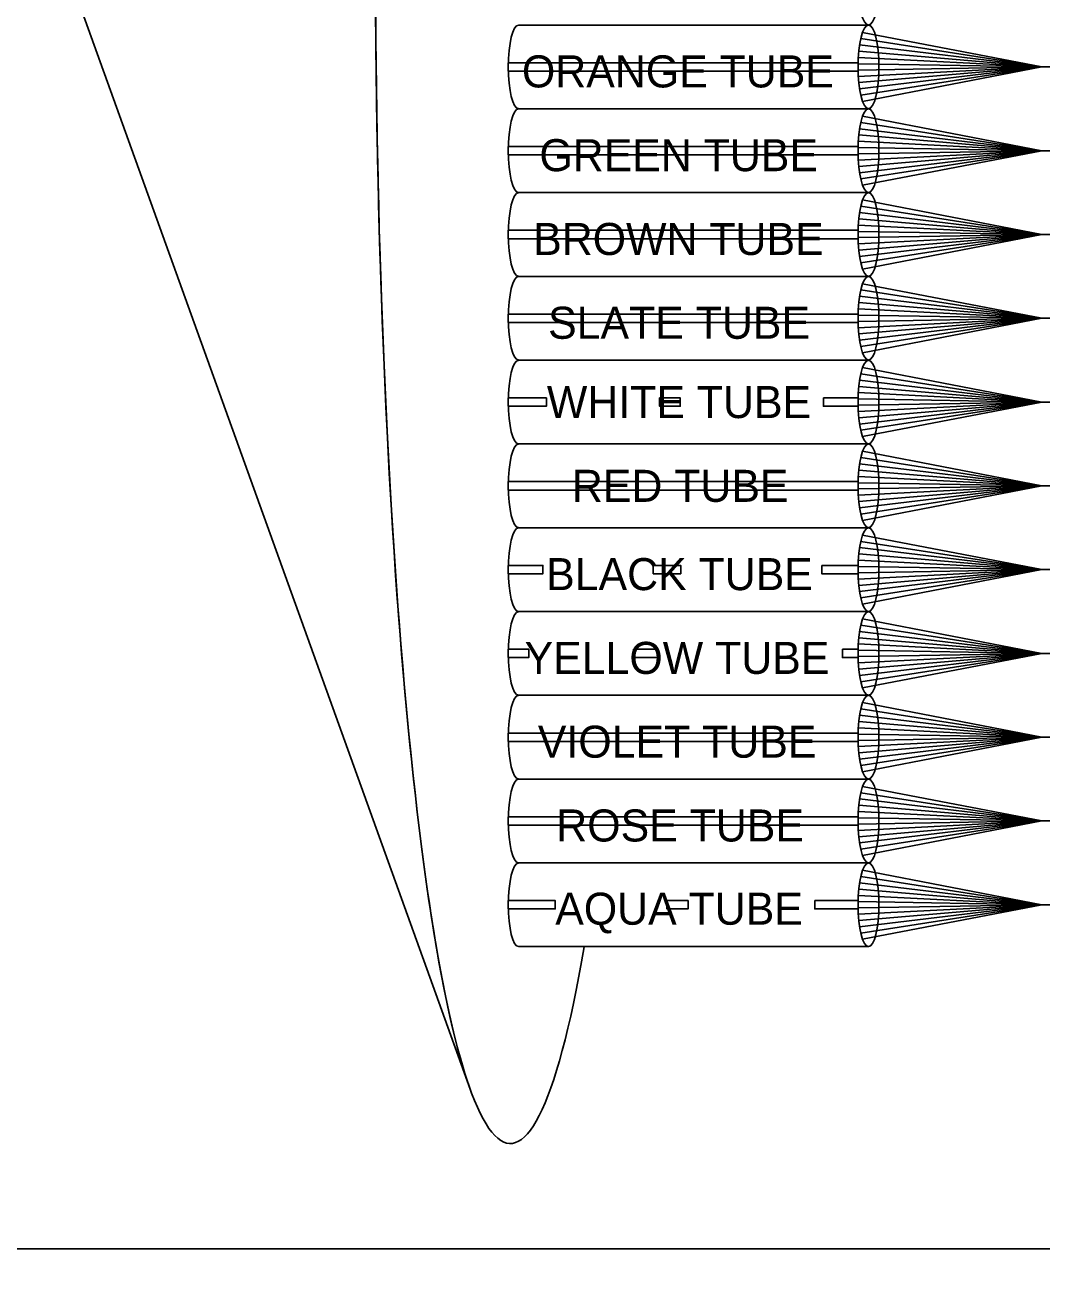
# Model space of a CAD drawing. Extents: x 1805893 to 1833564, y 708898 to 716199.
# Drawn here: x 1831609.4 to 1831682.2, y 715310.4 to 715400 of the extents above; entities that cross this region are included whole.
import ezdxf

# ---------------------------------------------------------------- set-up
doc = ezdxf.new("R2010")
doc.units = 0
doc.layers.add('BR_P_Sub_Hidden', color=7, linetype='Continuous')
doc.layers.add('SH_Data', color=7, linetype='Continuous')

msp = doc.modelspace()

# ---------------------------------------------------------------- linework, layer by layer
at = {"layer": 'BR_P_Sub_Hidden'}
msp.add_lwpolyline([(1831583.98, 715635.505), (1831928.325, 715635.505), (1831928.325, 715312.356), (1831583.98, 715312.356)], close=True, dxfattribs=at)
at = {"layer": 'SH_Data'}
for p, q in [((1831644.773, 715399.988), (1831669.823, 715399.988)), ((1831682.244, 715396.988), (1831669.27, 715399.013)), ((1831682.244, 715396.988), (1831669.4, 715399.463)), ((1831682.244, 715396.988), (1831669.128, 715398.113)), ((1831682.244, 715396.988), (1831669.185, 715398.563)), ((1831682.244, 715396.988), (1831669.076, 715397.213)), ((1831682.244, 715396.988), (1831669.076, 715396.763)), ((1831682.244, 715396.988), (1831669.093, 715397.663)), ((1831682.244, 715396.988), (1831669.093, 715396.313)), ((1831682.244, 715396.988), (1831669.128, 715395.863)), ((1831682.244, 715396.988), (1831669.185, 715395.413)), ((1831682.244, 715396.988), (1831669.27, 715394.963)), ((1831682.244, 715396.988), (1831669.4, 715394.513)), ((1831682.244, 715396.988), (1831717.244, 715396.988)), ((1831682.244, 715396.988), (1831717.244, 715396.988)), ((1831644.773, 715393.988), (1831669.823, 715393.988)), ((1831669.823, 715393.988), (1831644.773, 715393.988)), ((1831682.244, 715390.988), (1831669.4, 715393.463)), ((1831682.244, 715390.988), (1831669.185, 715392.563)), ((1831682.244, 715390.988), (1831669.27, 715393.013)), ((1831682.244, 715390.988), (1831669.093, 715391.663)), ((1831682.244, 715390.988), (1831669.128, 715392.113)), ((1831682.244, 715390.988), (1831669.076, 715391.213)), ((1831682.244, 715390.988), (1831669.076, 715390.763)), ((1831682.244, 715390.988), (1831669.093, 715390.313)), ((1831682.244, 715390.988), (1831669.128, 715389.863)), ((1831682.244, 715390.988), (1831669.185, 715389.413)), ((1831682.244, 715390.988), (1831669.27, 715388.963)), ((1831682.244, 715390.988), (1831669.4, 715388.513)), ((1831682.244, 715390.988), (1831717.244, 715390.988)), ((1831682.244, 715390.988), (1831717.244, 715390.988)), ((1831669.823, 715387.988), (1831644.773, 715387.988)), ((1831644.773, 715387.988), (1831669.823, 715387.988)), ((1831682.244, 715384.988), (1831669.4, 715387.463)), ((1831682.244, 715384.988), (1831669.185, 715386.563)), ((1831682.244, 715384.988), (1831669.27, 715387.013)), ((1831682.244, 715384.988), (1831669.093, 715385.663)), ((1831682.244, 715384.988), (1831669.128, 715386.113)), ((1831682.244, 715384.988), (1831669.076, 715385.213)), ((1831682.244, 715384.988), (1831669.076, 715384.763)), ((1831682.244, 715384.988), (1831669.093, 715384.313)), ((1831682.244, 715384.988), (1831669.128, 715383.863)), ((1831682.244, 715384.988), (1831669.185, 715383.413)), ((1831682.244, 715384.988), (1831669.27, 715382.963)), ((1831682.244, 715384.988), (1831669.4, 715382.513)), ((1831682.244, 715384.988), (1831717.244, 715384.988)), ((1831682.244, 715384.988), (1831717.244, 715384.988)), ((1831669.823, 715381.988), (1831644.773, 715381.988)), ((1831644.773, 715381.988), (1831669.823, 715381.988)), ((1831682.244, 715378.988), (1831669.27, 715381.013)), ((1831682.244, 715378.988), (1831669.4, 715381.463)), ((1831682.244, 715378.988), (1831669.128, 715380.113)), ((1831682.244, 715378.988), (1831669.185, 715380.563)), ((1831682.244, 715378.988), (1831669.076, 715379.213)), ((1831682.244, 715378.988), (1831669.076, 715378.763)), ((1831682.244, 715378.988), (1831669.093, 715379.663)), ((1831682.244, 715378.988), (1831669.093, 715378.313)), ((1831682.244, 715378.988), (1831669.128, 715377.863)), ((1831682.244, 715378.988), (1831669.185, 715377.413)), ((1831682.244, 715378.988), (1831669.27, 715376.963)), ((1831682.244, 715378.988), (1831669.4, 715376.513)), ((1831682.244, 715378.988), (1831717.244, 715378.988)), ((1831682.244, 715378.988), (1831717.244, 715378.988)), ((1831669.823, 715375.988), (1831644.773, 715375.988)), ((1831644.773, 715375.988), (1831669.823, 715375.988)), ((1831682.244, 715372.988), (1831669.4, 715375.463)), ((1831682.244, 715372.988), (1831669.185, 715374.563)), ((1831682.244, 715372.988), (1831669.27, 715375.013)), ((1831682.244, 715372.988), (1831669.093, 715373.663)), ((1831682.244, 715372.988), (1831669.128, 715374.113)), ((1831682.244, 715372.988), (1831669.076, 715373.213)), ((1831682.244, 715372.988), (1831669.076, 715372.763)), ((1831682.244, 715372.988), (1831669.093, 715372.313)), ((1831682.244, 715372.988), (1831669.128, 715371.863)), ((1831682.244, 715372.988), (1831669.185, 715371.413)), ((1831682.244, 715372.988), (1831669.27, 715370.963)), ((1831682.244, 715372.988), (1831669.4, 715370.513)), ((1831682.244, 715372.988), (1831717.244, 715372.988)), ((1831669.823, 715369.988), (1831644.773, 715369.988)), ((1831644.773, 715369.988), (1831669.823, 715369.988)), ((1831682.244, 715366.988), (1831669.4, 715369.463)), ((1831682.244, 715366.988), (1831669.185, 715368.563)), ((1831682.244, 715366.988), (1831669.27, 715369.013)), ((1831682.244, 715366.988), (1831669.093, 715367.663)), ((1831682.244, 715366.988), (1831669.128, 715368.113)), ((1831682.244, 715366.988), (1831669.076, 715367.213)), ((1831682.244, 715366.988), (1831669.076, 715366.763)), ((1831682.244, 715366.988), (1831669.093, 715366.313)), ((1831682.244, 715366.988), (1831669.128, 715365.863)), ((1831682.244, 715366.988), (1831669.185, 715365.413)), ((1831682.244, 715366.988), (1831669.27, 715364.963)), ((1831682.244, 715366.988), (1831669.4, 715364.513)), ((1831717.244, 715366.988), (1831682.244, 715366.988)), ((1831682.244, 715366.988), (1831717.244, 715366.988)), ((1831669.823, 715363.988), (1831644.773, 715363.988)), ((1831644.773, 715363.988), (1831669.823, 715363.988)), ((1831682.244, 715360.988), (1831669.27, 715363.013)), ((1831682.244, 715360.988), (1831669.4, 715363.463)), ((1831682.244, 715360.988), (1831669.128, 715362.113)), ((1831682.244, 715360.988), (1831669.185, 715362.563)), ((1831682.244, 715360.988), (1831669.076, 715361.213)), ((1831682.244, 715360.988), (1831669.093, 715361.663)), ((1831682.244, 715360.988), (1831669.076, 715360.763)), ((1831682.244, 715360.988), (1831669.093, 715360.313)), ((1831682.244, 715360.988), (1831669.128, 715359.863)), ((1831682.244, 715360.988), (1831669.185, 715359.413)), ((1831682.244, 715360.988), (1831669.27, 715358.963)), ((1831682.244, 715360.988), (1831669.4, 715358.513)), ((1831682.244, 715360.988), (1831717.244, 715360.988)), ((1831682.244, 715360.988), (1831717.244, 715360.988)), ((1831644.773, 715357.988), (1831669.823, 715357.988)), ((1831669.823, 715357.988), (1831644.773, 715357.988)), ((1831682.244, 715354.988), (1831669.27, 715357.013)), ((1831682.244, 715354.988), (1831669.4, 715357.463)), ((1831682.244, 715354.988), (1831669.128, 715356.113)), ((1831682.244, 715354.988), (1831669.185, 715356.563)), ((1831682.244, 715354.988), (1831669.076, 715355.213)), ((1831682.244, 715354.988), (1831669.076, 715354.763)), ((1831682.244, 715354.988), (1831669.093, 715355.663)), ((1831682.244, 715354.988), (1831669.093, 715354.313)), ((1831682.244, 715354.988), (1831669.128, 715353.863)), ((1831682.244, 715354.988), (1831669.185, 715353.413)), ((1831682.244, 715354.988), (1831669.27, 715352.963)), ((1831682.244, 715354.988), (1831669.4, 715352.513)), ((1831682.244, 715354.988), (1831717.244, 715354.988)), ((1831682.244, 715354.988), (1831717.244, 715354.988)), ((1831669.823, 715351.988), (1831644.773, 715351.988)), ((1831644.773, 715351.988), (1831669.823, 715351.988)), ((1831682.244, 715348.988), (1831669.4, 715351.463)), ((1831682.244, 715348.988), (1831669.185, 715350.563)), ((1831682.244, 715348.988), (1831669.27, 715351.013)), ((1831682.244, 715348.988), (1831669.093, 715349.663)), ((1831682.244, 715348.988), (1831669.128, 715350.113)), ((1831682.244, 715348.988), (1831669.076, 715349.213)), ((1831682.244, 715348.988), (1831669.076, 715348.763)), ((1831682.244, 715348.988), (1831669.093, 715348.313)), ((1831682.244, 715348.988), (1831669.128, 715347.863)), ((1831682.244, 715348.988), (1831669.185, 715347.413)), ((1831682.244, 715348.988), (1831669.27, 715346.963)), ((1831682.244, 715348.988), (1831669.4, 715346.513)), ((1831682.244, 715348.988), (1831717.244, 715348.988)), ((1831682.244, 715348.988), (1831717.244, 715348.988)), ((1831669.823, 715345.988), (1831644.773, 715345.988)), ((1831644.773, 715345.988), (1831669.823, 715345.988)), ((1831682.244, 715342.988), (1831669.27, 715345.013)), ((1831682.244, 715342.988), (1831669.4, 715345.463)), ((1831682.244, 715342.988), (1831669.128, 715344.113)), ((1831682.244, 715342.988), (1831669.185, 715344.563)), ((1831682.244, 715342.988), (1831669.076, 715343.213)), ((1831682.244, 715342.988), (1831669.093, 715343.663)), ((1831682.244, 715342.988), (1831669.076, 715342.763)), ((1831682.244, 715342.988), (1831669.093, 715342.313)), ((1831682.244, 715342.988), (1831669.128, 715341.863)), ((1831682.244, 715342.988), (1831669.185, 715341.413)), ((1831682.244, 715342.988), (1831669.27, 715340.963)), ((1831682.244, 715342.988), (1831669.4, 715340.513)), ((1831682.244, 715342.988), (1831717.244, 715342.988)), ((1831682.244, 715342.988), (1831717.244, 715342.988)), ((1831669.823, 715339.988), (1831644.773, 715339.988)), ((1831644.773, 715339.988), (1831669.823, 715339.988)), ((1831682.244, 715336.988), (1831669.27, 715339.013)), ((1831682.244, 715336.988), (1831669.4, 715339.463)), ((1831682.244, 715336.988), (1831669.128, 715338.113)), ((1831682.244, 715336.988), (1831669.185, 715338.563)), ((1831682.244, 715336.988), (1831669.076, 715337.213)), ((1831682.244, 715336.988), (1831669.076, 715336.763)), ((1831682.244, 715336.988), (1831669.093, 715337.663)), ((1831682.244, 715336.988), (1831669.093, 715336.313)), ((1831682.244, 715336.988), (1831669.128, 715335.863)), ((1831682.244, 715336.988), (1831669.185, 715335.413)), ((1831682.244, 715336.988), (1831669.27, 715334.963)), ((1831682.244, 715336.988), (1831669.4, 715334.513)), ((1831682.244, 715336.988), (1831717.244, 715336.988)), ((1831669.823, 715333.988), (1831644.773, 715333.988)), ((1831644.773, 715333.988), (1831669.823, 715333.988)), ((1831669.823, 715333.988), (1831649.465, 715333.988))]:
    msp.add_line(p, q, dxfattribs=at)
msp.add_lwpolyline([(1831641.297, 715488.184), (1831611.704, 715405.988), (1831641.297, 715323.792)], dxfattribs=at)
msp.add_lwpolyline([(1831641.297, 715488.184), (1831611.704, 715405.988), (1831641.297, 715323.792)], dxfattribs=at)
for points in [[(1831644.027, 715397.288), (1831669.075, 715397.288), (1831669.075, 715396.688), (1831644.027, 715396.688)], [(1831644.027, 715391.288), (1831669.075, 715391.288), (1831669.075, 715390.688), (1831644.027, 715390.688)], [(1831644.027, 715385.288), (1831669.075, 715385.288), (1831669.075, 715384.688), (1831644.027, 715384.688)], [(1831644.027, 715379.288), (1831669.075, 715379.288), (1831669.075, 715378.688), (1831644.027, 715378.688)], [(1831644.027, 715373.288), (1831646.753, 715373.288), (1831646.753, 715372.688), (1831644.027, 715372.688)], [(1831654.859, 715373.288), (1831656.343, 715373.288), (1831656.343, 715372.688), (1831654.859, 715372.688)], [(1831666.59, 715373.288), (1831669.077, 715373.288), (1831669.077, 715372.688), (1831666.59, 715372.688)], [(1831644.027, 715367.288), (1831669.075, 715367.288), (1831669.075, 715366.688), (1831644.027, 715366.688)], [(1831644.027, 715361.288), (1831646.504, 715361.288), (1831646.504, 715360.688), (1831644.027, 715360.688)], [(1831654.404, 715361.288), (1831656.376, 715361.288), (1831656.376, 715360.688), (1831654.404, 715360.688)], [(1831666.469, 715361.288), (1831669.077, 715361.288), (1831669.077, 715360.688), (1831666.469, 715360.688)], [(1831644.027, 715355.288), (1831645.491, 715355.288), (1831645.491, 715354.688), (1831644.027, 715354.688)], [(1831652.991, 715355.288), (1831654.711, 715355.288), (1831654.711, 715354.688), (1831652.991, 715354.688)], [(1831667.949, 715355.288), (1831669.077, 715355.288), (1831669.077, 715354.688), (1831667.949, 715354.688)], [(1831644.027, 715349.288), (1831669.075, 715349.288), (1831669.075, 715348.688), (1831644.027, 715348.688)], [(1831644.027, 715343.288), (1831669.075, 715343.288), (1831669.075, 715342.688), (1831644.027, 715342.688)], [(1831644.027, 715337.288), (1831647.395, 715337.288), (1831647.395, 715336.688), (1831644.027, 715336.688)], [(1831655.39, 715337.288), (1831656.908, 715337.288), (1831656.908, 715336.688), (1831655.39, 715336.688)], [(1831665.974, 715337.288), (1831669.077, 715337.288), (1831669.077, 715336.688), (1831665.974, 715336.688)]]:
    msp.add_lwpolyline(points, close=True, dxfattribs=at)
for centre, major_axis, ratio, start_param, end_param in [((1831644.17, 715405.988), (0, -86.094), 0.112175, 2.561295, 6.863483), ((1831644.17, 715405.988), (0, -86.094), 0.112175, 2.561295, 6.863483), ((1831644.17, 715405.988), (0, -86.094), 0.112175, 3.443628, 5.98115), ((1831644.773, 715396.988), (0, -3), 0.25, 3.141593, 6.283185), ((1831644.773, 715396.988), (0, -3), 0.25, 3.141593, 6.283185), ((1831669.823, 715396.988), (0, -3), 0.25, 3.141593, 6.283185), ((1831644.773, 715390.988), (0, -3), 0.25, 3.141593, 6.283185), ((1831644.773, 715390.988), (0, -3), 0.25, 3.141593, 6.283185), ((1831669.823, 715390.988), (0, -3), 0.25, 3.141593, 6.283185), ((1831644.773, 715384.988), (0, -3), 0.25, 3.141593, 6.283185), ((1831644.773, 715384.988), (0, -3), 0.25, 3.141593, 6.283185), ((1831669.823, 715384.988), (0, -3), 0.25, 3.141593, 6.283185), ((1831644.773, 715378.988), (0, -3), 0.25, 3.141593, 6.283185), ((1831644.773, 715378.988), (0, -3), 0.25, 3.141593, 6.283185), ((1831669.823, 715378.988), (0, -3), 0.25, 3.141593, 6.283185), ((1831644.773, 715372.988), (0, -3), 0.25, 3.141593, 6.283185), ((1831644.773, 715372.988), (0, -3), 0.25, 3.141593, 6.283185), ((1831669.823, 715372.988), (0, -3), 0.25, 3.141593, 6.283185), ((1831644.773, 715366.988), (0, -3), 0.25, 3.141593, 6.283185), ((1831644.773, 715366.988), (0, -3), 0.25, 3.141593, 6.283185), ((1831669.823, 715366.988), (0, -3), 0.25, 3.141593, 6.283185), ((1831644.773, 715360.988), (0, -3), 0.25, 3.141593, 6.283185), ((1831644.773, 715360.988), (0, -3), 0.25, 3.141593, 6.283185), ((1831669.823, 715360.988), (0, -3), 0.25, 3.141593, 6.283185), ((1831644.773, 715354.988), (0, -3), 0.25, 3.141593, 6.283185), ((1831644.773, 715354.988), (0, -3), 0.25, 3.141593, 6.283185), ((1831669.823, 715354.988), (0, -3), 0.25, 3.141593, 6.283185), ((1831644.773, 715348.988), (0, -3), 0.25, 3.141593, 6.283185), ((1831644.773, 715348.988), (0, -3), 0.25, 3.141593, 6.283185), ((1831669.823, 715348.988), (0, -3), 0.25, 3.141593, 6.283185), ((1831644.773, 715342.988), (0, -3), 0.25, 3.141593, 6.283185), ((1831644.773, 715342.988), (0, -3), 0.25, 3.141593, 6.283185), ((1831669.823, 715342.988), (0, -3), 0.25, 3.141593, 6.283185), ((1831644.773, 715336.988), (0, -3), 0.25, 3.141593, 6.283185), ((1831644.773, 715336.988), (0, -3), 0.25, 3.141593, 6.283185), ((1831669.823, 715336.988), (0, -3), 0.25, 3.141593, 6.283185)]:
    msp.add_ellipse(centre, major_axis=major_axis, ratio=ratio, start_param=start_param, end_param=end_param, dxfattribs=at)
for centre in [(1831669.823, 715402.988), (1831669.823, 715396.988), (1831669.823, 715390.988), (1831669.823, 715384.988), (1831669.823, 715378.988), (1831669.823, 715372.988), (1831669.823, 715366.988), (1831669.823, 715360.988), (1831669.823, 715354.988), (1831669.823, 715348.988), (1831669.823, 715342.988), (1831669.823, 715336.988)]:
    msp.add_ellipse(centre, major_axis=(0, -3), ratio=0.25, dxfattribs=at)

# ---------------------------------------------------------------- texts
for s, height, p in [('ORANGE TUBE', 2.29468, (1831645.008, 715395.519)), ('GREEN TUBE', 2.2947, (1831646.255, 715389.519)), ('BROWN TUBE', 2.2947, (1831645.811, 715383.519)), ('SLATE TUBE', 2.2947, (1831646.877, 715377.519)), ('WHITE TUBE', 2.2947, (1831646.792, 715371.841)), ('RED TUBE', 2.2947, (1831648.58, 715365.841)), ('BLACK TUBE', 2.2947, (1831646.738, 715359.519)), ('YELLOW TUBE', 2.29468, (1831645.194, 715353.519)), ('VIOLET TUBE', 2.29468, (1831646.144, 715347.519)), ('ROSE TUBE', 2.2947, (1831647.467, 715341.519)), ('AQUA TUBE', 2.2947, (1831647.391, 715335.559))]:
    msp.add_text(s, height=height, dxfattribs=at).set_placement(p)

doc.saveas('drawing.dxf')
